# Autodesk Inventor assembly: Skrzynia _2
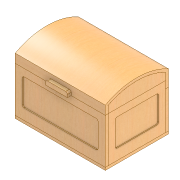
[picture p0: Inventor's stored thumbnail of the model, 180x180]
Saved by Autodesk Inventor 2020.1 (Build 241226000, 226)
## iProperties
Manager: www.cadconsulting.pl
Company: Fabian Stasiak CAD Consulting
Created: 2019-06
Part Number: Skrzynia _2
Document SubType Name: Assembly
Designer: F.Stasiak
Author: F.Stasiak
Subject: Zbiór ćwiczeń. Autodesk Inventor 2020. Kurs podstawowy
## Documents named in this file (3)
- C:\2020_Kurs_podstawowy\R6 Zespoły\Wiązania\Skrzynia I\Skrzynia _2.iam
- C:\2020_Kurs_podstawowy\R6 Zespoły\Wiązania\Skrzynia I\Wieko_2.iam
- C:\2020_Kurs_podstawowy\R6 Zespoły\Wiązania\Skrzynia I\Pudło_1.iam
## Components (2 placed, 2 different names)
1. Pudło_1:1 [sub-assembly]
2. Wieko_2:1 [sub-assembly]
